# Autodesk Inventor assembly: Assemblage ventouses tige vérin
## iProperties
Created: 2011-02
Part Number: Assemblage ventouses tige vérin
Document SubType Name: Assembly
Designer: eric
Norme de conversion: IGES 5.3
Nom du fichier: No Iges File Name specified
Préprocesseur: Autodesk Inventor 2011
Postprocesseur: Build: 342, Release: 2008 SP3 - Date: Tue 05/27/2008
Unités envoyées: MM
Incertitude: 0.01
Author: eric
